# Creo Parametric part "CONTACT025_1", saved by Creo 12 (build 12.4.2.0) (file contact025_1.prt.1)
Units: Custom; MM, KILOGRAM, SECS

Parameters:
  PTC_WM_ITERATION = "0"
  PTC_WM_VERSION = "-.0"
  PTC_WM_LIFECYCLE_STATE = "In Work"
  PTC_WM_LIFECYCLE = "MO_CADDocument"
  PTC_WM_CREATED_BY = "Maximilian Roepper (Z0017RMS: MO)"
  PTC_WM_CREATED_ON = "18-Sep-26 11:36:42 AM"
  PTC_WM_MODIFIED_BY = "Maximilian Roepper (Z0017RMS: MO)"
  PTC_WM_MODIFIED_ON = "18-Sep-26 11:36:46 AM"
  PDMLINKNUMBER = "PDM000071455250"
  PTC_WM_NAME = "contact025_1.prt"
  PTC_WM_NUMBER = "PDM000071455250"

Other parameters: WEIGHT, WEIGHT_FACTOR, WEIGHT_ADD, _MASS_TEMP, _DIFF_TEMP, MC_ERRORS, SUPPLIER

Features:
  1. coordinate system
  2. datum plane "PRT_YZ"
  3. datum plane "PRT_XY"
  4. datum plane "PRT_XZ"
  5. coordinate system
  6. datum axis
  7. datum axis
  8. datum axis
  9. coordinate system
  10. imported feature

Other named items: PRT, SIEMENS_MO, DRW_VIEW_ORG, PRT_X, PRT_Y, PRT_Z, CS0, ROUGH_GROB

Layers: 00_STD_CSYS-KSYS, 01_STD_PLANES-EBENEN, 02_STD_AXES-ACHSEN, 03_STD_CSYS-KSYS, 24_IMPORT_FEAT-IMPORT_KE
